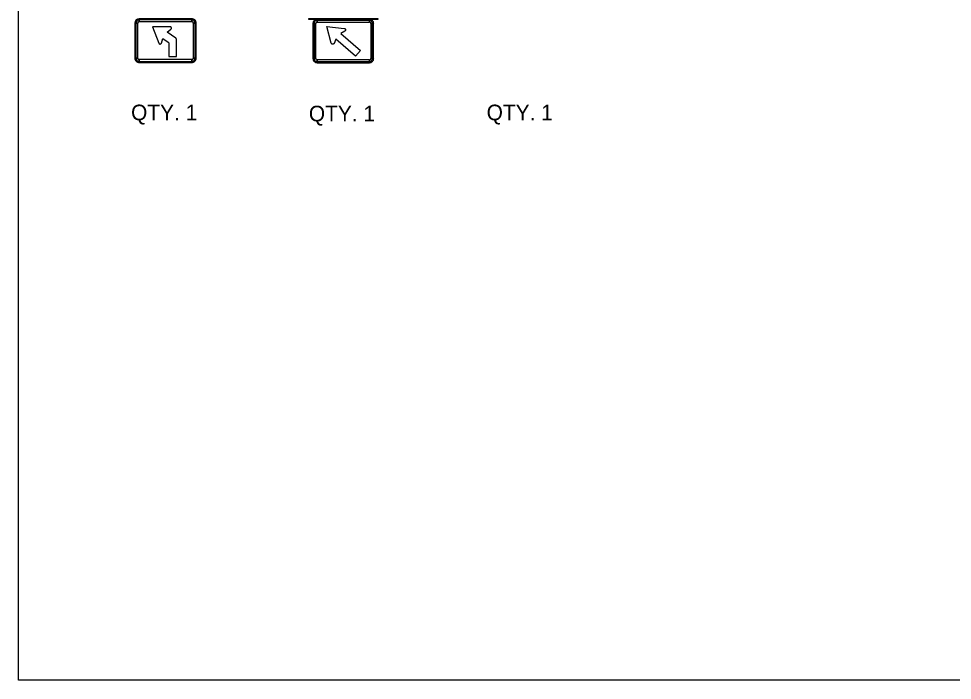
# Model space of a CAD drawing. Extents: x 10133 to 81668, y 5524 to 11018.
# Drawn here: x 24533 to 25877, y 7924 to 8876 of the extents above; entities that cross this region are included whole.
import ezdxf

# ---------------------------------------------------------------- set-up
doc = ezdxf.new("R2010")
doc.units = 0
for name, color, linetype in [('DisCLMLSUR', 7, 'Continuous'), ('DisPropROW', 7, 'Continuous'), ('Level 3', 7, 'Continuous')]:
    doc.layers.add(name, color=color, linetype=linetype)

msp = doc.modelspace()

# ---------------------------------------------------------------- linework, layer by layer
at = {"layer": 'DisPropROW'}
for p, q in [((24781.8, 8876.4), (24706.1, 8876.4)), ((24706.1, 8872.2), (24706.1, 8874.8)), ((24781.8, 8874.8), (24781.8, 8872.2)), ((25050, 8876.4), (24950, 8876.4)), ((25043.7, 8876.4), (24956.2, 8876.4)), ((25037.5, 8875.6), (24962.5, 8875.6)), ((24962.5, 8871.4), (24962.5, 8874)), ((25009.3, 8876.4), (24990.7, 8876.4)), ((25037.5, 8874), (25037.5, 8871.4)), ((24699.8, 8870.1), (24699.8, 8819.7)), ((24701.4, 8870.1), (24704, 8870.1)), ((24750.4, 8864.9), (24725.1, 8864.9)), ((24725.1, 8864.9), (24734.2, 8841.2)), ((24746.4, 8856.9), (24751.7, 8861.1)), ((24783.9, 8870.1), (24786.5, 8870.1)), ((24788.1, 8819.7), (24788.1, 8870.1)), ((24956.2, 8869.3), (24956.2, 8819.3)), ((24957.8, 8869.3), (24960.4, 8869.3)), ((24982.7, 8841.1), (24976.5, 8865.4)), ((24976.5, 8865.4), (25001.4, 8862.4)), ((25039.6, 8869.3), (25042.2, 8869.3)), ((25043.7, 8819.3), (25043.7, 8869.3)), ((24738.2, 8841.4), (24740.2, 8847.9)), ((24740.2, 8847.9), (24748, 8842.4)), ((24758.7, 8848.5), (24746.4, 8856.9)), ((24989.4, 8846.9), (24986.6, 8840.8)), ((25017.4, 8822.3), (24989.4, 8846.9)), ((25002.3, 8858.6), (24996.6, 8855.1)), ((24996.6, 8855.1), (25024.6, 8830.5)), ((24748.7, 8841.4), (24748.7, 8841.1)), ((24748.7, 8841.1), (24748.7, 8822)), ((24704, 8819.7), (24701.4, 8819.7)), ((24786.5, 8819.7), (24783.9, 8819.7)), ((25024.6, 8830.5), (25017.4, 8822.3)), ((24706.1, 8815), (24706.1, 8817.6)), ((24706.1, 8813.4), (24781.8, 8813.4)), ((24781.8, 8817.6), (24781.8, 8815)), ((24960.4, 8819.3), (24957.8, 8819.3)), ((24962.5, 8814.6), (24962.5, 8817.2)), ((24962.5, 8813.1), (25037.5, 8813.1)), ((25037.5, 8817.2), (25037.5, 8814.6)), ((25042.2, 8819.3), (25039.6, 8819.3))]:
    msp.add_line(p, q, dxfattribs=at)
for points in [[(24781.8, 8874.8), (24706.1, 8874.8), (24706.1, 8872.2), (24781.8, 8872.2), (24781.8, 8874.8)], [(25037.5, 8874), (24962.5, 8874), (24962.5, 8871.4), (25037.5, 8871.4), (25037.5, 8874)], [(24701.4, 8870.1), (24701.4, 8819.7), (24704, 8819.7), (24704, 8870.1), (24701.4, 8870.1)], [(24786.5, 8819.7), (24786.5, 8870.1), (24783.9, 8870.1), (24783.9, 8819.7), (24786.5, 8819.7)], [(24957.8, 8869.3), (24957.8, 8819.3), (24960.4, 8819.3), (24960.4, 8869.3), (24957.8, 8869.3)], [(25042.2, 8819.3), (25042.2, 8869.3), (25039.6, 8869.3), (25039.6, 8819.3), (25042.2, 8819.3)], [(24706.1, 8815), (24781.8, 8815), (24781.8, 8817.6), (24706.1, 8817.6), (24706.1, 8815)], [(24962.5, 8814.6), (25037.5, 8814.6), (25037.5, 8817.2), (24962.5, 8817.2), (24962.5, 8814.6)]]:
    msp.add_lwpolyline(points, close=True, dxfattribs=at)
for points in [[(24950, 8876.4), (24950, 8875.6), (25050, 8875.6), (25050, 8876.4)], [(24956.2, 8876.4), (24956.2, 8875.6), (25043.7, 8875.6), (25043.7, 8876.4)], [(24751.7, 8861.1), (24751.9, 8861.3), (24752.1, 8861.5), (24752.2, 8861.8), (24752.3, 8862), (24752.4, 8862.3), (24752.5, 8862.5), (24752.5, 8862.8), (24752.5, 8863.1), (24752.4, 8863.4), (24752.3, 8863.6), (24752.2, 8863.8), (24752.1, 8864.1), (24751.9, 8864.3), (24751.7, 8864.5), (24751.5, 8864.6), (24751.2, 8864.8), (24750.9, 8864.8), (24750.7, 8864.9), (24750.4, 8864.9)], [(25001.4, 8862.4), (25001.7, 8862.4), (25001.9, 8862.3), (25002.2, 8862.2), (25002.4, 8862.1), (25002.6, 8861.9), (25002.8, 8861.7), (25003, 8861.5), (25003.1, 8861.2), (25003.2, 8861), (25003.2, 8860.7), (25003.3, 8860.4), (25003.2, 8860.2), (25003.2, 8859.9), (25003.1, 8859.6), (25003, 8859.4), (25002.9, 8859.2), (25002.7, 8859), (25002.5, 8858.8), (25002.3, 8858.6)], [(24748.7, 8822), (24759.7, 8822), (24759.7, 8846.6)], [(24759.7, 8846.6), (24759.7, 8846.8), (24759.7, 8847.1), (24759.6, 8847.4), (24759.5, 8847.6), (24759.3, 8847.9), (24759.1, 8848.1), (24759, 8848.3), (24758.7, 8848.5)], [(24734.2, 8841.2), (24734.3, 8841), (24734.5, 8840.7), (24734.6, 8840.5), (24734.8, 8840.4), (24735.1, 8840.2), (24735.3, 8840.1), (24735.6, 8840), (24735.8, 8839.9), (24736.1, 8839.9), (24736.4, 8839.9), (24736.6, 8840), (24736.9, 8840), (24737.1, 8840.1), (24737.4, 8840.3), (24737.6, 8840.5), (24737.8, 8840.7), (24737.9, 8840.9), (24738.1, 8841.1), (24738.2, 8841.4)], [(24748, 8842.4), (24748.2, 8842.3), (24748.4, 8842.1), (24748.5, 8841.9), (24748.6, 8841.6), (24748.7, 8841.4)], [(24986.6, 8840.8), (24986.5, 8840.6), (24986.3, 8840.3), (24986.2, 8840.1), (24986, 8840), (24985.7, 8839.8), (24985.5, 8839.7), (24985.2, 8839.6), (24984.9, 8839.6), (24984.7, 8839.6), (24984.4, 8839.6), (24984.1, 8839.6), (24983.9, 8839.7), (24983.7, 8839.9), (24983.4, 8840), (24983.2, 8840.2), (24983.1, 8840.4), (24982.9, 8840.6), (24982.8, 8840.9), (24982.7, 8841.1)]]:
    msp.add_lwpolyline(points, dxfattribs=at)
for centre, radius, start, end in [((24706.1, 8870.1), 6.3, 90.0002, 179.9998), ((24706.1, 8870.1), 4.73, 90.0002, 179.9998), ((24781.8, 8870.1), 6.3, 0, 90.0002), ((24781.8, 8870.1), 4.73, 0, 90.0002), ((24962.5, 8869.3), 6.25, 90.0002, 179.9998), ((24962.5, 8869.3), 4.69, 90.0002, 179.9998), ((25000, 8925.6), 50, 259.3001, 280.6999), ((25037.5, 8869.3), 6.25, 0, 90.0002), ((25037.5, 8869.3), 4.69, 0, 90.0002), ((24706.1, 8870.1), 2.1, 90.0002, 179.9998), ((24781.8, 8870.1), 2.1, 0, 90.0002), ((24962.5, 8869.3), 2.08, 90.0002, 179.9998), ((25037.5, 8869.3), 2.08, 0, 90.0002), ((24706.1, 8819.7), 6.3, 179.9998, 270.0001), ((24706.1, 8819.7), 4.73, 179.9998, 270.0001), ((24706.1, 8819.7), 2.1, 179.9998, 270.0001), ((24781.8, 8819.7), 6.3, 270.0001, 0.0003), ((24781.8, 8819.7), 4.73, 270.0001, 0.0003), ((24781.8, 8819.7), 2.1, 270.0001, 0.0003), ((24962.5, 8819.3), 6.25, 179.9998, 270.0001), ((24962.5, 8819.3), 4.69, 179.9998, 270.0001), ((24962.5, 8819.3), 2.08, 179.9998, 270.0001), ((25037.5, 8819.3), 6.25, 270.0001, 0.0003), ((25037.5, 8819.3), 4.69, 270.0001, 0.0003), ((25037.5, 8819.3), 2.08, 270.0001, 0.0003)]:
    msp.add_arc(centre, radius, start, end, dxfattribs=at)
at = {"layer": 'Level 3'}
msp.add_lwpolyline([(24532.5, 9944), (27667.5, 9944), (27667.5, 7924), (24532.5, 7924)], close=True, dxfattribs=at)

# ---------------------------------------------------------------- texts
at = {"layer": 'DisCLMLSUR'}
for p in [(24694.4, 8730.2), (25206.4, 8730.2), (24950.4, 8728.6)]:
    msp.add_text('QTY. 1', height=22.5, dxfattribs=at).set_placement(p)

doc.saveas('drawing.dxf')
